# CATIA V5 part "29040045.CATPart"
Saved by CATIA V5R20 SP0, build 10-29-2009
Part number: 29040045
Definition: NONE
Nomenclature: 29040045
Source: Unknown
Description: 29040045
Bounding box of the stored display mesh (mm): x -22.5 to 44.548, y -34 to 68.548, z -24 to 24
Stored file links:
  C:\Users\Utente\Desktop\IO LAVORO\3D X SITO CF\X SITO\PLASTICA\RF1\29040045.CATPart
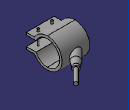
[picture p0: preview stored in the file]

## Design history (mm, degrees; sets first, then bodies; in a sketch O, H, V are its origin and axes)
Body1 "29040045" (main body)
  Solid1: solid without history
